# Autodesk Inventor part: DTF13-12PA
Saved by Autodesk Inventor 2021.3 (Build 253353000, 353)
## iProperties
Created: 2023-03
Part Number: DTF13-12PA
Material: Generic
Document SubType Name: Modeling
Designer: AdminForWorker
Density: 1 g/cm^3
Appearance: Default
Title: DTF13-12PA
Author: AdminForWorker
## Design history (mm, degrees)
feature "Body1"
body "Solid1"
